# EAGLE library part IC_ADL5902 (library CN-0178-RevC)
50MHz to 9GHz, 65 dB TruPower Detector.
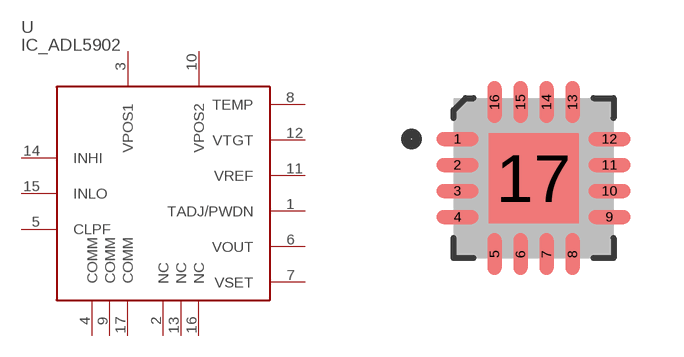
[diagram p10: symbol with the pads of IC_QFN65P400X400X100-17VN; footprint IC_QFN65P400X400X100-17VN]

Designator prefix -

## IC_ADL5902_LFCSP_VQ  [IC_QFN65P400X400X100-17VN]
1  TADJ/PWDN  pas
2  NC  pas
3  VPOS1  pas
4  COMM  pas
5  CLPF  pas
6  VOUT  pas
7  VSET  pas
8  TEMP  pas
9  COMM  pas
10  VPOS2  pas
11  VREF  pas
12  VTGT  pas
13  NC  pas
14  INHI  pas
15  INLO  pas
16  NC  pas
17  COMM  pas

## Footprint IC_QFN65P400X400X100-17VN (pad centres in mm)
(QFN-17) 0.65mm pitch; 4.00mm L X 4.00mm W X 1.00mm H body w/thermal tab; JEDEC MO-220VGGC
smd 1.05 x 0.35: 1 -1.9,0.975; 2 -1.9,0.325; 3 -1.9,-0.325; 4 -1.9,-0.975; 9 1.9,-0.975; 10 1.9,-0.325; 11 1.9,0.325; 12 1.9,0.975
smd 0.35 x 1.05: 5 -0.975,-1.9; 6 -0.325,-1.9; 7 0.325,-1.9; 8 0.975,-1.9; 13 0.975,1.9; 14 0.325,1.9; 15 -0.325,1.9; 16 -0.975,1.9
smd 2.25 x 2.25: 17 0,0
